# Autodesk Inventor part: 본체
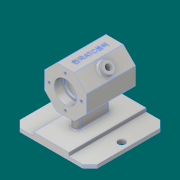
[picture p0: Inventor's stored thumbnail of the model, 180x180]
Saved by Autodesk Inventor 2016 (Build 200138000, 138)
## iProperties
Created: 2018-06
Part Number: 본체
Material: 알루미늄 6061
Document SubType Name: Modeling
Designer: 605-03
Mass: 552.311 g
Surface Area: 603.221 cm^2
Volume: 204.56 cm^3
Density: 2.7 g/cm^3
Appearance: 알루미늄 - 평지
Author: 605-03
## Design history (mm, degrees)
sketch "스케치1" dims "d0" = 60
  geometry: L1 (12.426, 30)-(30, 12.426); L2 (30, 12.426)-(30, -12.426); L3 (30, -12.426)-(12.426, -30); L4 (12.426, -30)-(-12.426, -30); L5 (-12.426, -30)-(-30, -12.426); L6 (-30, -12.426)-(-30, 12.426); L7 (-30, 12.426)-(-12.426, 30); L8 (-12.426, 30)-(12.426, 30); 4 further points
  constraints: 16 end point, 2 coincident, 1 midpoint, 1 vertical alignment, 19 other
  dimensions: "d1" = 17.57359 horizontal distance of L2.end L3.end
extrude "돌출1" new body sketch "스케치1" stored distance "d2" = 70; taper "d3" = 0 deg
sketch "스케치2"
  geometry: C1 r 16 at (0, 0); 1 further point
  constraints: 1 centre point, 1 coincident
  dimensions: "d4" = 32 diameter of C1
hole "구멍1" sketch "스케치2" at (0, 0) diameter "d5" = 32; stored, may be unused: countersink angle "d9" = 90 deg, drill point angle "d11" = 0 deg; dims "d6" = 6, "d7" = 4, "d8" = 2, "d10" = 12
sketch "스케치3"
  geometry: C1 r 16 at (0, 0) reference; C2 r 14 at (0, 0)
  constraints: 1 centre point, 1 coincident
  dimensions: "d12" = 28 diameter of C2
hole "구멍2" sketch "스케치3" at (0, 0) diameter "d13" = 28; stored, may be unused: countersink angle "d17" = 90 deg, drill point angle "d19" = 0 deg; dims "d14" = 6, "d15" = 4, "d16" = 2, "d18" = 3
sketch "스케치4"
  geometry: C1 r 14 at (0, 0) reference; C2 r 25 at (0, 0)
  constraints: 1 centre point, 1 coincident
  dimensions: "d20" = 50 diameter of C2
hole "구멍3" sketch "스케치4" at (0, 0) diameter "d21" = 50; stored, may be unused: countersink angle "d25" = 90 deg, drill point angle "d27" = 0 deg; dims "d22" = 6, "d23" = 4, "d24" = 2, "d26" = 40
fillet "모깎기1" dims "d28" = 0.3
fillet "모깎기2" dims "d29" = 3
fillet "모깎기3" dims "d30" = 1
sketch "스케치5" dims "d31" = 46
  geometry: C1 r 16 at (0, 0) reference; 2 further points
  constraints: 2 horizontal alignment, 1 coincident, 2 other
hole "구멍4" sketch "스케치5" at (23, 0) diameter "d32" = 3.242; stored, may be unused: countersink angle "d36" = 90 deg, drill point angle "d38" = 118 deg; dims "d33" = 8, "d34" = 4, "d35" = 2, "d37" = 10
node "작업 평면1"
sketch "스케치6"
  geometry: L1 (55, 55)-(55, -55); L2 (55, -55)-(-55, -55); L3 (-55, -55)-(-55, 55); L4 (-55, 55)-(55, 55); L5 (0, 0)-(0, -63.241); L6 (0, 0)-(61.775, 0); 2 further points
  constraints: 12 end point, 2 horizontal, 2 midpoint, 2 perpendicular, 2 point on line, 2 vertical
  dimensions: "d43" = 110 distance of L1.end L2.end; "d44" = 110 distance of L1.start L1.end
extrude "돌출2" join sketch "스케치6" distance "d46" = 5; taper "d47" = 0 deg
chamfer "모따기1" distance "d48" = 10; stored, may be unused: second distance "d49" = 2, angle "d50" = 45 deg
chamfer "모따기2" distance "d51" = 10; stored, may be unused: second distance "d52" = 2, angle "d53" = 45 deg
chamfer "모따기3" distance "d54" = 10; stored, may be unused: second distance "d55" = 2, angle "d56" = 45 deg
chamfer "모따기4" distance "d57" = 10; stored, may be unused: second distance "d58" = 2, angle "d59" = 45 deg
sketch "스케치7"
  geometry: L1 (45, 55)-(-45, 55) reference; L2 (-55, 45)-(-55, -45) reference; L3 (-45, -55)-(45, -55) reference; L4 (55, -45)-(55, 45) reference; L5 (45, -55)-(-45, -55) reference; L6 (-45, 55)-(45, 55) reference; L7 (-25, -55)-(-25, 55); L8 (25, 55)-(25, -55); 1 further point
  constraints: 4 end point, 4 point on line, 2 perpendicular
  dimensions: "d60" = 30 distance between parallel lines of L2 L7; "d61" = 30 distance between parallel lines of L4 L8
extrude "돌출3" join sketch "스케치7" distance "d62" = 5; taper "d63" = 0 deg
sketch "스케치8"
  geometry: L1 (0, -19)-(0, 19); L2 (5, -19)-(5, 19); L3 (-5, 19)-(-5, -19); A1 r 5 centre (0, -19) between (-5, -19) and (5, -19); A2 r 5 centre (0, 19) between (5, 19) and (-5, 19); 2 further points
  constraints: 6 end point, 4 point on circle, 3 coincident, 2 centre point, 2 tangent, 2 vertical, 1 midpoint, 1 parallel
  dimensions: "d64" = 38 distance of L1.start L1.end; "d65" = 10 diameter of A2; "d66" = 10 diameter of A1
extrude "돌출4" join sketch "스케치8" stored distance "d67" = 5; taper "d68" = 0 deg
fillet "모깎기4" dims "d69" = 2
sketch "스케치9"
  geometry: L1 (55, -45)-(55, 45) reference; L2 (55, 0)-(-55, 0); L3 (-55, -45)-(-55, 45) reference; C1 r 5 at (45, 0); 2 further points
  constraints: 2 end point, 2 midpoint, 1 centre point, 1 coincident, 1 point on line
  dimensions: "d70" = 10 distance from line of L1 point (45, 0); "d71" = 10 diameter of C1
hole "구멍5" sketch "스케치9" at (45, 0) diameter "d72" = 10; stored, may be unused: countersink angle "d76" = 90 deg, drill point angle "d78" = 0 deg; dims "d73" = 8, "d74" = 4, "d75" = 2, "d77" = 10
sketch "스케치10"
  geometry: C1 r 8 at (12.012, 35); 1 further point
  constraints: 1 centre point, 1 coincident
  dimensions: "d79" = 16 diameter of C1
extrude "돌출5" join sketch "스케치10" distance "d80" = 7; taper "d81" = 0 deg
sketch "스케치11"
  geometry: C1 r 8 at (0, 0) reference; C2 r 4 at (0, 0)
  constraints: 1 centre point, 1 coincident
  dimensions: "d82" = 8 diameter of C2
hole "구멍6" sketch "스케치11" at (0, 0) diameter "d83" = 8; stored, may be unused: countersink angle "d87" = 90 deg, drill point angle "d89" = 0 deg; dims "d84" = 8, "d85" = 4, "d86" = 2, "d88" = 10
fillet "모깎기5" dims "d90" = 3
sketch "스케치12"
  geometry: L1 (24.024, -70)-(0, -70) reference; L2 (-17.695, -70)-(-17.695, 0) reference; 2 further points
  constraints: 1 other
  dimensions: "d91" = 30 distance from line of L2 point (12.305, -35); "d92" = 35 distance from line of L1 point (12.305, -35)
feature "엠보싱1" sketch "스케치12" dims "d0" = 60, "d1" = 17.57359, "d93" = 0.5, "d94" = 0
node "솔리드1"
mirror "대칭1"
mirror "대칭2"
pattern_circular "원형 패턴1" dims angle "d40" = 360 deg
mirror "대칭3"
mirror "대칭4"
other parameters: "d42" = -62
